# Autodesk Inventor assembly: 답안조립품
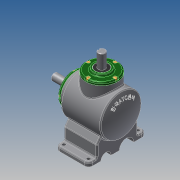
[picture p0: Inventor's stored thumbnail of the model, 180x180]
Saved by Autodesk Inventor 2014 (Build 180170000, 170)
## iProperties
Created: 2018-08
Part Number: 답안조립품
Document SubType Name: Assembly
Designer: kb542
Author: kb542
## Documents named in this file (14)
- C:\Users\kb542\Desktop\480807V1009\답안조립품.iam
- C:\Users\kb542\Desktop\480807V1009\본체.ipt
- C:\Users\kb542\Desktop\480807V1009\메인 축.ipt
- 메인 축.ipt
- C:\Users\kb542\Desktop\480807V1009\키 5x5.ipt
- C:\Users\kb542\Desktop\480807V1009\메인 베벨기어.ipt
- C:\Users\kb542\Desktop\480807V1009\베어링 6203.ipt
- C:\Users\kb542\Desktop\480807V1009\커버.ipt
- C:\Users\kb542\Desktop\480807V1009\오일실 17 32 8.ipt
- C:\Users\kb542\Desktop\480807V1009\볼트 M4.ipt
- C:\Users\kb542\Desktop\480807V1009\서브 축.ipt
- 서브 축.ipt
- C:\Users\kb542\Desktop\480807V1009\키 4x4.ipt
- C:\Users\kb542\Desktop\480807V1009\서브 베벨기어.ipt
